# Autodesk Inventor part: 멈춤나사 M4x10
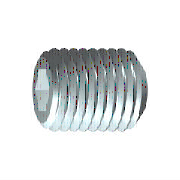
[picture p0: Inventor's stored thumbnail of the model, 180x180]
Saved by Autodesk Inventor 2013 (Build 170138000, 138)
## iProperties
Created: 2012-02
Part Number: 멈춤나사 M4x10
Material: 강철, 연강
Description: 6각 소켓 머리 없는 멈춤 나사
Document SubType Name: Modeling
Standard: KS B 1028
Designer: mduedu
Standards Organization: KS
Language: ko-KR
Size Designation: 납작점M4x10
Categories: <MemberInstance><Categories><Category DisplayName="조임쇠" InternalName="e4da775c-781d-43d5-af7c-5136215cf5a6" Mnemonic="FSTN"><Category DisplayName="볼트" InternalN
Density: 1 g/cm^3
IsCustomPart: 1
Author: mduedu
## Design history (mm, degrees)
sketch "스케치1"
  geometry: L1 (0, 0)-(6.833, 0); L2 (10, 1.155)-(10, 2); L3 (10, 2)-(0, 2); L4 (10, 1.155)-(7.5, 1.155); L5 (7.5, 1.155)-(6.833, 0); L6 (0, -0.4)-(0, 2.4) reference; L7 (0, 2)-(0, 0)
  constraints: 13 end point, 3 parallel, 1 collinear, 1 perpendicular, 1 point on line
  dimensions: "d0" = 2.5 distance of L2.start L4.end (= INTI); "d1" = 60 deg angle of L5 L1; "d2" = 4 diameter of L3 L1 (= NND); "d3" = 2.3094 diameter of L4 L1 (= 1.1547 x SW); "d5" = 10 distance from line of L2 L3.end (= NLG)
revolve "본체" sketch "스케치1" stored, may be unused: angle "d6" = 90 deg
sketch "스케치2"
  geometry: L1 (-0.577, 1)-(0.577, 1); L2 (0.577, 1)-(1.155, 0); L3 (1.155, 0)-(0.577, -1); L4 (0.577, -1)-(-0.577, -1); L5 (-0.577, -1)-(-1.155, 0); L6 (-1.155, 0)-(-0.577, 1); A1 r 1.155 centre (0, 0) between (-0.577, 1) and (0.577, 1) reference; 2 further points
  constraints: 12 end point, 2 point on circle, 1 coincident, 1 horizontal, 11 other
extrude "슬롯" join sketch "스케치2" taper "d9" = 0 deg; stored distance "d21" = 10
workaxis "Work Axis1"
workplane "Work Plane1"
body "Solid1"
chamfer "모따기1" distance "d7" = 0.42941 (= -0.5 x GD1 + 0.5 x NND); stored, may be unused: angle "d8" = 45 deg (= FAWI), second distance "d29" = 0.42941 (= -0.5 x GD1 + 0.5 x NND)
feature "스레드" dims "d11" = 10 (= NLG), "d12" = 0
chamfer "모따기2" distance "d13" = 0.42941 (= -0.5 x GD1 + 0.5 x NND); stored, may be unused: angle "d14" = 45 deg (= FAWI), second distance "d30" = 0.42941 (= -0.5 x GD1 + 0.5 x NND)
other parameters: "NND" = 4 [user parameter; used in 5 equation terms], "NLG" = 10 [user parameter; used in 2 equation terms], "INTI" = 2.5 [user parameter; used in 1 equation term], "FAWI" = 45 deg [user parameter; used in 2 equation terms], "SW" = 2 [user parameter; used in 2 equation terms], "GD1" = 3.14117 (= THREADDIA - 1.2269 x PTC) [user parameter; used in 4 equation terms], "d4" = 0, "FAWI1" = 45 deg [user parameter], "d15" = 0, "d31" = 0, "GUL" = 0.42941 (= 0.61345 x PTC) [user parameter], "SPD" = 2.5 [user parameter], "TPU" = 14.28571 (computed from PTC) [user parameter], "TOA" = 30 deg [user parameter], "THREADDIA" = 4 [user parameter; used in 1 equation term], "PTC" = 0.7 [user parameter; used in 4 equation terms], "GAL" = 0.42941 (= 0.61345 x PTC) [user parameter], "E0" = 2.31 (= 1.155 x SW) [user parameter]
